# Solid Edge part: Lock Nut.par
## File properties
Author: Vicky Raina
Template: normal.par
Last saved by: Administrator
Revision: 4
Application: Solid Edge
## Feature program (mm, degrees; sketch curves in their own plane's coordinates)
sketch for "unnamed Protrusion 1" plane through (0, 0, 0) normal (0, 0, 1) x-axis (1, 0, 0)
  line (-7.5, 12.9904) -> (-15, 0)
  line (-15, 0) -> (-7.5, -12.9904)
  line (-7.5, -12.9904) -> (7.5, -12.9904)
  line (7.5, -12.9904) -> (15, 0)
  line (15, 0) -> (7.5, 12.9904)
  line (7.5, 12.9904) -> (-7.5, 12.9904)
extrude "unnamed Protrusion 1" add finite 8 symmetric
sketch for "unnamed RevolvedCutout 1" plane through (0, 0, 0) normal (0, -1, 0) x-axis (1, 0, 0)
  arc centre (12, 1) radius 3 from (12, 4) to (15, 1) cw
  line (15, 4) -> (15, 1)
  line (15, 4) -> (12, 4)
revolve "unnamed RevolvedCutout 1" cut full turn 360 deg
mirror "unnamed Mirror 1" of "unnamed RevolvedCutout 1" about plane through (0, 0, 0) normal (0, 0, 1)
revolve "unnamed RevolvedCutout 2" cut full turn 360 deg
sketch for "unnamed Hole 1" plane through (0, 0, 4) normal (0, 0, 1) x-axis (0, 1, 0)
  hole centre (0, 0) bore radius 6
hole "unnamed Hole 1" through
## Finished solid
Body 1: solid body, 11 faces, 22 edges, 12 vertices.
  Faces by surface: plane 8, torus 2, cylinder 1
  Edges by curve: intersection 12, line 6, circle 4
Bounding box of the edges (mm; curved faces can reach further): 30.000 x 25.981 x 8.000, from (-15, -12.9904, -4) to (15, 12.9904, 4).
Cylindrical faces by radius (mm): R6 x1
Toroidal faces (ring radius, tube radius in mm): R12 r3 x2
Planar faces by outward normal: +y 1, +z 1, -y 1, -z 1, oblique 4
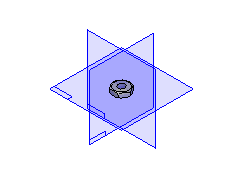
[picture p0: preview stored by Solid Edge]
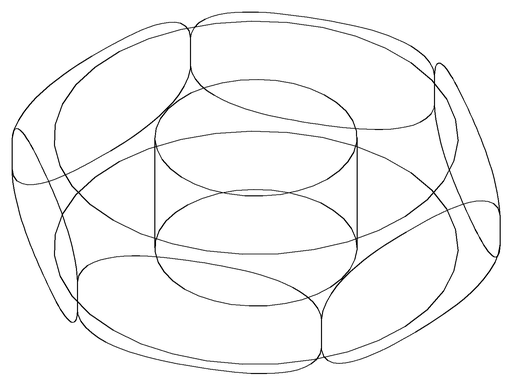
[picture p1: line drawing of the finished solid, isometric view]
